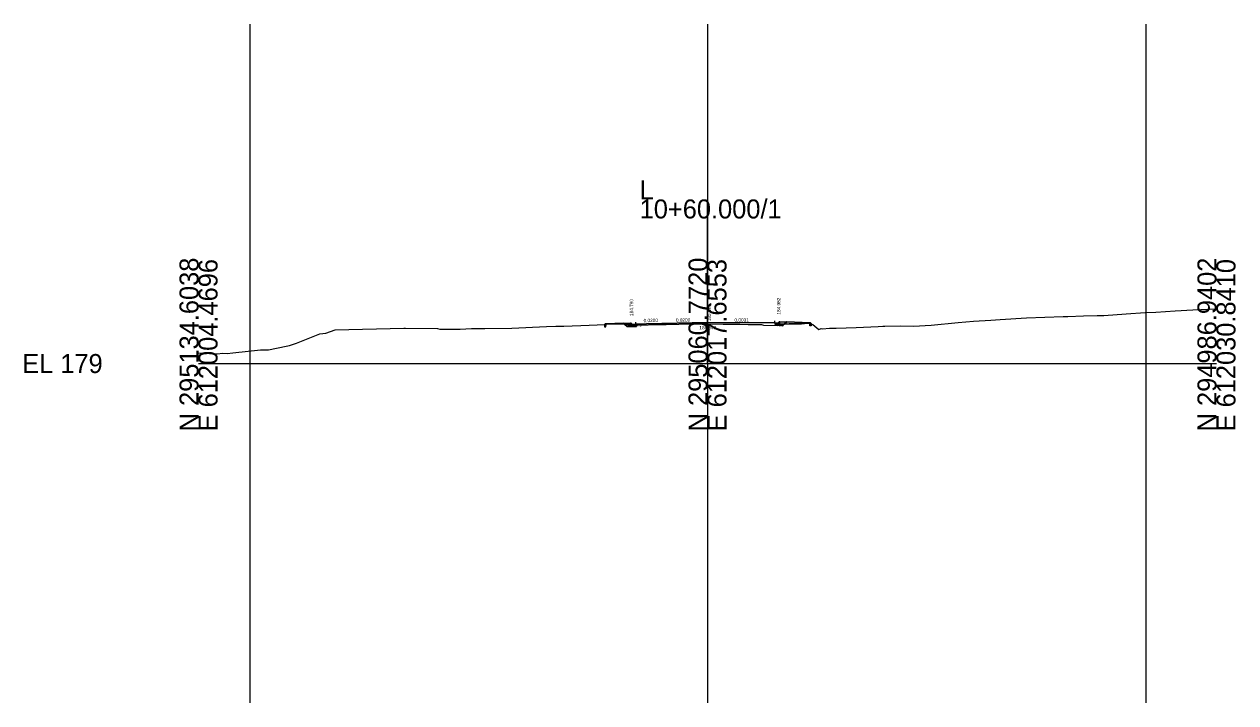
# Model space of a CAD drawing. Extents: x -81 to 616364, y 450 to 299952.
# Drawn here: x 535426.7 to 535605.2, y 116298.4 to 116398.4 of the extents above; entities that cross this region are included whole.
import ezdxf

# ---------------------------------------------------------------- set-up
doc = ezdxf.new("R2010")
doc.units = 0
for name, color, linetype in [('Exist XS Ground Line', 7, 'Continuous'), ('Old_Level_10', 7, 'Continuous'), ('Old_Level_17', 7, 'Continuous'), ('Old_Level_63', 7, 'Continuous'), ('Prop XS Dump Level', 7, 'Continuous'), ('Prop XS Earthwork Shape', 7, 'Continuous'), ('Prop XS EOT Tick Mark', 7, 'Continuous'), ('Prop XS Exc Vertical Line 1', 7, 'Continuous'), ('Prop XS Exc Vertical Line 2', 7, 'Continuous'), ('Prop XS Exc Vertical Line 3', 7, 'Continuous'), ('Prop XS Finish Grade', 7, 'Continuous'), ('Prop XS Finish Grade Concrete', 7, 'Continuous'), ('Prop XS Finish Grade Earthwork', 7, 'Continuous'), ('Prop XS Finish Grade Pavement', 7, 'Continuous'), ('Prop XS Pvmt Edge Slope', 7, 'Continuous'), ('Prop XS Side Slope Text', 7, 'Continuous'), ('Prop XS Subgrade Concrete', 7, 'Continuous'), ('Prop XS Subgrade Earthwork', 7, 'Continuous')]:
    doc.layers.add(name, color=color, linetype=linetype)

msp = doc.modelspace()

# ---------------------------------------------------------------- linework, layer by layer
at = {"layer": 'Exist XS Ground Line'}
for points in [[(535553.5, 116353.89), (535555.78, 116353.9), (535557.73, 116353.89), (535560.3, 116354.02), (535564.31, 116354.41), (535566.58, 116354.6), (535569.09, 116354.77), (535570.49, 116354.87), (535574.39, 116355.1), (535579.79, 116355.27), (535580.46, 116355.3), (535582.79, 116355.4), (535584.8, 116355.44), (535585.75, 116355.46), (535589.03, 116355.68), (535591.86, 116355.9), (535593.43, 116355.95), (535596.29, 116356.15), (535598.9, 116356.29), (535602.36, 116356.42)], [(535452.36, 116349.93), (535454.83, 116349.78), (535455.08, 116349.81), (535455.94, 116349.89), (535456.56, 116349.86), (535457.42, 116349.96), (535461.5, 116350.39), (535462.69, 116350.38), (535465.28, 116350.92), (535465.77, 116351.03), (535466.81, 116351.37), (535470.25, 116352.73), (535471.14, 116352.85), (535472.51, 116353.35), (535482.62, 116353.56), (535482.84, 116353.55), (535487.58, 116353.53), (535487.94, 116353.44), (535488.91, 116353.44), (535490.91, 116353.42), (535492.57, 116353.5), (535494.53, 116353.52), (535498.52, 116353.58), (535503.64, 116353.8), (535504.99, 116353.85), (535505.43, 116353.86), (535506.19, 116353.88), (535509.92, 116354.03), (535512.26, 116354.1), (535512.4, 116354.1), (535512.55, 116354.2), (535515.87, 116354.15), (535516.6, 116354.13), (535516.9, 116354.13), (535517.05, 116354.03), (535520.25, 116354.11), (535520.36, 116354.13), (535521.26, 116354.13), (535525, 116354.2), (535525.17, 116354.2), (535527.27, 116354.21), (535529.68, 116354.18), (535532.14, 116354.15), (535533.37, 116354.13), (535535.3, 116354.09), (535535.6, 116354.03), (535537.71, 116353.98), (535537.87, 116354.14), (535539.4, 116354.19), (535539.87, 116354.21), (535541.2, 116354.22), (535542.14, 116354.31), (535542.36, 116354.33), (535542.51, 116354.23), (535542.62, 116354.23), (535542.88, 116354.11), (535543.78, 116353.4), (535544.09, 116353.51), (535544.31, 116353.45), (535545.34, 116353.57), (535546.31, 116353.59), (535549.25, 116353.65), (535552.53, 116353.84), (535553.22, 116353.87), (535553.5, 116353.89)]]:
    msp.add_lwpolyline(points, dxfattribs=at)
at = {"layer": 'Old_Level_10'}
for p, q in [((535542.45, 116354.26), (535542.45, 116354.36)), ((535512.37, 116354.1), (535512.37, 116354.22))]:
    msp.add_line(p, q, dxfattribs=at)
msp.add_arc((535512.38, 116354.17), 0.00196, 145.5013, 214.4987, dxfattribs=at)
at = {"layer": 'Old_Level_17'}
for p, q in [((535542.45, 116354.35), (535542.46, 116354.36)), ((535542.48, 116354.35), (535542.45, 116354.34)), ((535542.46, 116354.36), (535542.51, 116354.36)), ((535542.47, 116354.36), (535542.48, 116354.35)), ((535542.54, 116354.35), (535542.65, 116354.24)), ((535542.54, 116354.35), (535542.54, 116354.35)), ((535512.29, 116354.21), (535512.17, 116354.1)), ((535512.17, 116354.1), (535512.17, 116353.77)), ((535512.37, 116354.07), (535512.17, 116354.07)), ((535512.17, 116354.02), (535512.19, 116354.02)), ((535512.18, 116354), (535512.17, 116354)), ((535512.18, 116353.93), (535512.17, 116353.93)), ((535512.17, 116353.91), (535512.19, 116353.9)), ((535512.17, 116353.77), (535512.37, 116353.77)), ((535512.19, 116354.02), (535512.18, 116354)), ((535512.19, 116353.9), (535512.18, 116353.93)), ((535512.24, 116354.11), (535512.27, 116354.12)), ((535512.28, 116354.1), (535512.24, 116354.11)), ((535512.24, 116353.82), (535512.27, 116353.83)), ((535512.28, 116353.81), (535512.24, 116353.82)), ((535512.27, 116354.12), (535512.28, 116354.1)), ((535512.27, 116353.83), (535512.28, 116353.81)), ((535512.29, 116354.21), (535512.29, 116354.21)), ((535512.37, 116354.22), (535512.32, 116354.22)), ((535512.36, 116354.22), (535512.35, 116354.21)), ((535512.35, 116354.21), (535512.37, 116354.21)), ((535512.37, 116354.01), (535512.35, 116354.04)), ((535512.35, 116354.04), (535512.37, 116354.04)), ((535512.36, 116353.95), (535512.35, 116353.92)), ((535512.35, 116353.92), (535512.37, 116353.92)), ((535512.37, 116353.92), (535512.36, 116353.95)), ((535512.37, 116354.22), (535512.37, 116354.22)), ((535512.37, 116353.77), (535512.37, 116354.1)), ((535542.45, 116353.91), (535542.45, 116354.26)), ((535542.45, 116354.21), (535542.65, 116354.21)), ((535542.48, 116354.17), (535542.45, 116354.18)), ((535542.45, 116354.15), (535542.48, 116354.17)), ((535542.45, 116354.06), (535542.47, 116354.08)), ((535542.48, 116354.05), (535542.45, 116354.05)), ((535542.65, 116353.91), (535542.45, 116353.91)), ((535542.47, 116354.08), (535542.48, 116354.05)), ((535542.56, 116354.26), (535542.55, 116354.24)), ((535542.55, 116354.24), (535542.59, 116354.25)), ((535542.56, 116353.97), (535542.55, 116353.95)), ((535542.55, 116353.95), (535542.59, 116353.96)), ((535542.59, 116354.25), (535542.56, 116354.26)), ((535542.59, 116353.96), (535542.56, 116353.97)), ((535542.63, 116354.04), (535542.65, 116354.07)), ((535542.65, 116354.05), (535542.63, 116354.04)), ((535542.64, 116354.16), (535542.65, 116354.14)), ((535542.65, 116354.15), (535542.64, 116354.16)), ((535542.65, 116354.24), (535542.65, 116353.91)), ((535542.65, 116354.14), (535542.65, 116354.14)), ((535542.65, 116354.07), (535542.65, 116354.07))]:
    msp.add_line(p, q, dxfattribs=at)
for centre in [(535512.18, 116353.96), (535512.2, 116354.08), (535512.2, 116353.79), (535512.22, 116354.12), (535512.21, 116353.98), (535512.22, 116353.83), (535512.23, 116354.08), (535512.22, 116354.04), (535512.22, 116353.88), (535512.23, 116353.79), (535512.25, 116353.94), (535512.26, 116354.15), (535512.27, 116354.06), (535512.26, 116353.86), (535512.27, 116354.18), (535512.27, 116354.02), (535512.27, 116353.98), (535512.28, 116353.97), (535512.27, 116353.89), (535512.28, 116353.93), (535512.3, 116354.16), (535512.3, 116354.1), (535512.3, 116354.02), (535512.3, 116353.87), (535512.3, 116353.81), (535512.32, 116354.07), (535512.33, 116353.97), (535512.32, 116353.95), (535512.35, 116354.12), (535512.35, 116353.83), (535512.35, 116354.17), (535512.35, 116353.88), (535512.36, 116353.99), (535542.47, 116354.13), (535542.48, 116354.3), (535542.48, 116354.26), (535542.48, 116354.01), (535542.48, 116353.97), (535542.5, 116354.11), (535542.51, 116354.2), (535542.51, 116354.09), (535542.53, 116354.15), (535542.53, 116354.3), (535542.53, 116354.24), (535542.53, 116354.01), (535542.53, 116353.95), (535542.56, 116354.32), (535542.55, 116354.11), (535542.55, 116354.07), (535542.56, 116354.03), (535542.56, 116354.2), (535542.56, 116354.16), (535542.56, 116354.12), (535542.57, 116354.29), (535542.57, 116354), (535542.58, 116354.07), (535542.6, 116354.22), (535542.6, 116353.93), (535542.61, 116354.26), (535542.61, 116354.17), (535542.61, 116354.02), (535542.61, 116353.97), (535542.62, 116354.11), (535542.63, 116354.22), (535542.63, 116353.93), (535542.65, 116354.1)]:
    msp.add_circle(centre, 0.00196, dxfattribs=at)
for centre, radius, start, end in [((535542.46, 116354.36), 0.006, 90, 180), ((535542.51, 116354.31), 0.05, 45, 90), ((535512.18, 116353.87), 0.00196, 256.8767, 103.1233), ((535512.27, 116353.77), 0.00196, 24.915, 155.085), ((535512.32, 116354.17), 0.05, 90, 135), ((535512.32, 116353.78), 0.00196, 342.3416, 197.6584), ((535512.37, 116354.22), 0.006, 0, 90), ((535512.37, 116353.96), 0.00196, 17.8106, 342.1894), ((535542.45, 116354.31), 0.00196, 325.5013, 34.4987), ((535542.46, 116354.1), 0.00196, 197.8106, 162.1894), ((535542.51, 116353.91), 0.00196, 342.3416, 197.6584), ((535542.56, 116353.91), 0.00196, 24.915, 155.085), ((535542.65, 116354.01), 0.00196, 76.8767, 283.1233)]:
    msp.add_arc(centre, radius, start, end, dxfattribs=at)
at = {"layer": 'Old_Level_63'}
for p, q in [((535527.36, 116348.36), (535527.36, 116372.54)), ((535452.36, 116348.36), (535527.36, 116348.36)), ((535527.36, 116348.36), (535602.36, 116348.36))]:
    msp.add_line(p, q, dxfattribs=at)
at = {"layer": 'Prop XS Dump Level'}
for p, q in [((535518.36, 116354.21), (535527.36, 116354.39)), ((535527.36, 116354.39), (535537.26, 116354.36)), ((535516.76, 116354.18), (535518.36, 116354.21))]:
    msp.add_line(p, q, dxfattribs=at)
at = {"layer": 'Prop XS Earthwork Shape'}
for points in [[(535538.68, 116354.17), (535539.03, 116354.52), (535542.45, 116354.36), (535542.45, 116354.26), (535542.36, 116354.33), (535542.14, 116354.31), (535541.2, 116354.22), (535539.87, 116354.21), (535539.4, 116354.19)], [(535538.68, 116354.17), (535539.4, 116354.19), (535539.87, 116354.21), (535541.2, 116354.22), (535542.14, 116354.31), (535542.36, 116354.33), (535542.45, 116354.26), (535542.45, 116354.36), (535539.03, 116354.52)], [(535538.68, 116354.17), (535539.4, 116354.19), (535539.87, 116354.21), (535541.2, 116354.22), (535542.14, 116354.31), (535542.36, 116354.33), (535542.45, 116354.26), (535542.45, 116354.36), (535539.03, 116354.52)], [(535542.45, 116354.36), (535542.45, 116354.26), (535542.36, 116354.33), (535542.14, 116354.31), (535541.2, 116354.22), (535539.87, 116354.21), (535539.4, 116354.19), (535538.68, 116354.17), (535539.03, 116354.52)], [(535538.68, 116354.17), (535539.4, 116354.19), (535539.87, 116354.21), (535541.2, 116354.22), (535542.14, 116354.31), (535542.36, 116354.33), (535542.45, 116354.26), (535542.45, 116354.36), (535539.03, 116354.52)], [(535538.68, 116354.17), (535539.4, 116354.19), (535539.87, 116354.21), (535541.2, 116354.22), (535542.14, 116354.31), (535542.36, 116354.33), (535542.45, 116354.26), (535542.45, 116354.36), (535539.03, 116354.52)], [(535538.68, 116354.17), (535539.4, 116354.19), (535539.87, 116354.21), (535541.2, 116354.22), (535542.14, 116354.31), (535542.36, 116354.33), (535542.45, 116354.26), (535542.45, 116354.36), (535539.03, 116354.52)], [(535512.37, 116354.22), (535514.99, 116354.33), (535515.15, 116354.16), (535512.55, 116354.2), (535512.4, 116354.1), (535512.37, 116354.1)], [(535512.37, 116354.1), (535512.4, 116354.1), (535512.55, 116354.2), (535515.15, 116354.16), (535514.99, 116354.33), (535512.37, 116354.22)], [(535512.37, 116354.1), (535512.4, 116354.1), (535512.55, 116354.2), (535515.15, 116354.16), (535514.99, 116354.33), (535512.37, 116354.22)], [(535512.37, 116354.22), (535514.99, 116354.33), (535515.15, 116354.16), (535512.55, 116354.2), (535512.37, 116354.1)], [(535512.37, 116354.1), (535512.4, 116354.1), (535512.55, 116354.2), (535515.15, 116354.16), (535514.99, 116354.33), (535512.37, 116354.22)], [(535512.37, 116354.1), (535512.4, 116354.1), (535512.55, 116354.2), (535515.15, 116354.16), (535514.99, 116354.33), (535512.37, 116354.22)], [(535512.37, 116354.1), (535512.4, 116354.1), (535512.55, 116354.2), (535515.15, 116354.16), (535514.99, 116354.33), (535512.37, 116354.22)], [(535515.51, 116353.8), (535516.76, 116353.8), (535516.9, 116353.8), (535516.9, 116354.13), (535516.6, 116354.13), (535515.87, 116354.15), (535515.15, 116354.16)], [(535515.15, 116354.16), (535515.87, 116354.15), (535516.6, 116354.13), (535516.9, 116354.13), (535516.9, 116353.8), (535516.76, 116353.8), (535515.51, 116353.8)], [(535515.15, 116354.16), (535515.87, 116354.15), (535516.6, 116354.13), (535516.9, 116354.13), (535516.9, 116353.8), (535516.76, 116353.8), (535515.51, 116353.8)], [(535515.51, 116353.8), (535516.76, 116353.8), (535516.9, 116353.8), (535516.9, 116354.13), (535516.6, 116354.13), (535515.87, 116354.15), (535515.15, 116354.16)], [(535515.15, 116354.16), (535515.87, 116354.15), (535516.6, 116354.13), (535516.9, 116354.13), (535516.9, 116353.8), (535516.76, 116353.8), (535515.51, 116353.8)], [(535515.15, 116354.16), (535515.87, 116354.15), (535516.6, 116354.13), (535516.9, 116354.13), (535516.9, 116353.8), (535516.76, 116353.8), (535515.51, 116353.8)], [(535515.15, 116354.16), (535515.87, 116354.15), (535516.6, 116354.13), (535516.9, 116354.13), (535516.9, 116353.8), (535516.76, 116353.8), (535515.51, 116353.8)], [(535537.26, 116353.99), (535537.64, 116353.99), (535537.26, 116353.98)], [(535537.26, 116353.99), (535537.64, 116353.99), (535537.26, 116353.98)], [(535537.26, 116353.99), (535537.64, 116353.99), (535537.26, 116353.98)], [(535537.71, 116353.99), (535537.87, 116354.14), (535538.68, 116354.17), (535538.51, 116354)], [(535537.71, 116353.99), (535537.87, 116354.14), (535538.68, 116354.17), (535538.51, 116354)], [(535537.71, 116353.99), (535537.87, 116354.14), (535538.68, 116354.17), (535538.51, 116354)], [(535538.51, 116354), (535538.68, 116354.17), (535537.87, 116354.14), (535537.71, 116353.98)], [(535537.71, 116353.99), (535538.51, 116354), (535538.68, 116354.17), (535537.87, 116354.14)], [(535537.71, 116353.99), (535538.51, 116354), (535538.68, 116354.17), (535537.87, 116354.14)], [(535537.71, 116353.99), (535538.51, 116354), (535538.68, 116354.17), (535537.87, 116354.14)]]:
    msp.add_lwpolyline(points, close=True, dxfattribs=at)
at = {"layer": 'Prop XS EOT Tick Mark'}
for p, q in [((535516.76, 116354.48), (535516.76, 116354.18)), ((535537.26, 116354.36), (535537.26, 116354.67))]:
    msp.add_line(p, q, dxfattribs=at)
at = {"layer": 'Prop XS Exc Vertical Line 1'}
msp.add_line((535459.94, 116398.36), (535459.94, 116298.36), dxfattribs=at)
at = {"layer": 'Prop XS Exc Vertical Line 2'}
msp.add_line((535527.36, 116398.36), (535527.36, 116298.36), dxfattribs=at)
at = {"layer": 'Prop XS Exc Vertical Line 3'}
msp.add_line((535591.96, 116398.36), (535591.96, 116298.36), dxfattribs=at)
at = {"layer": 'Prop XS Finish Grade'}
for p, q in [((535538.01, 116354.5), (535539.03, 116354.52)), ((535514.99, 116354.33), (535516.01, 116354.3))]:
    msp.add_line(p, q, dxfattribs=at)
at = {"layer": 'Prop XS Finish Grade Concrete'}
for p, q in [((535537.26, 116354.36), (535537.79, 116354.35)), ((535537.79, 116354.35), (535537.83, 116354.36)), ((535537.83, 116354.36), (535537.85, 116354.38)), ((535537.85, 116354.38), (535537.87, 116354.46)), ((535537.87, 116354.46), (535537.9, 116354.49)), ((535537.94, 116354.5), (535537.9, 116354.49)), ((535538.01, 116354.5), (535537.94, 116354.5)), ((535516.09, 116354.3), (535516.01, 116354.3)), ((535516.13, 116354.3), (535516.09, 116354.3)), ((535516.13, 116354.3), (535516.15, 116354.27)), ((535516.15, 116354.27), (535516.18, 116354.19)), ((535516.18, 116354.19), (535516.2, 116354.16)), ((535516.2, 116354.16), (535516.24, 116354.16)), ((535516.24, 116354.16), (535516.76, 116354.18))]:
    msp.add_line(p, q, dxfattribs=at)
at = {"layer": 'Prop XS Finish Grade Earthwork'}
for p, q in [((535539.03, 116354.52), (535542.45, 116354.36)), ((535542.45, 116354.36), (535542.45, 116354.26)), ((535512.37, 116354.22), (535514.99, 116354.33)), ((535512.37, 116354.22), (535512.37, 116354.1))]:
    msp.add_line(p, q, dxfattribs=at)
at = {"layer": 'Prop XS Finish Grade Pavement'}
for p, q in [((535527.36, 116354.39), (535518.36, 116354.21)), ((535537.26, 116354.36), (535527.36, 116354.39)), ((535518.36, 116354.21), (535516.76, 116354.18))]:
    msp.add_line(p, q, dxfattribs=at)
at = {"layer": 'Prop XS Pvmt Edge Slope'}
for p, q in [((535515.51, 116353.8), (535515.71, 116354)), ((535515.71, 116354), (535516.01, 116354)), ((535538.01, 116354.19), (535538.31, 116354.2)), ((535538.31, 116354.2), (535538.51, 116354))]:
    msp.add_line(p, q, dxfattribs=at)
at = {"layer": 'Prop XS Subgrade Concrete'}
for p, q in [((535537.26, 116354.36), (535537.26, 116354.18)), ((535538.01, 116354.19), (535538.01, 116354.5)), ((535516.01, 116354.3), (535516.01, 116354)), ((535516.01, 116354), (535516.76, 116354)), ((535516.76, 116354), (535516.76, 116354.18)), ((535537.26, 116354.18), (535538.01, 116354.19))]:
    msp.add_line(p, q, dxfattribs=at)
at = {"layer": 'Prop XS Subgrade Earthwork'}
for p, q in [((535538.51, 116354), (535539.03, 116354.52)), ((535514.99, 116354.33), (535515.51, 116353.8)), ((535515.51, 116353.8), (535516.76, 116353.8)), ((535516.76, 116353.8), (535516.9, 116353.8)), ((535516.9, 116354.13), (535516.9, 116353.8)), ((535537.64, 116353.99), (535538.51, 116354))]:
    msp.add_line(p, q, dxfattribs=at)

# ---------------------------------------------------------------- texts
at = {"layer": 'Old_Level_63'}
for s, p in [('L', (535517.36, 116372.54)), ('10+60.000/1', (535517.36, 116369.74)), ('EL 179', (535426.37, 116346.96))]:
    msp.add_text(s, height=2.8, dxfattribs=at).set_placement(p)
for s, p in [('N 295134.6038', (535452.36, 116338.36)), ('E 612004.4696', (535455.16, 116338.36)), ('N 295060.7720', (535527.36, 116338.36)), ('E 612017.6553', (535530.16, 116338.36)), ('N 294986.9402', (535602.36, 116338.36)), ('E 612030.8410', (535605.16, 116338.36))]:
    msp.add_text(s, height=2.8, rotation=90, dxfattribs=at).set_placement(p)
at = {"layer": 'Prop XS Dump Level'}
for p in [(535516.9, 116353.83), (535537.87, 116353.84)]:
    msp.add_text('Eop', height=0.3, dxfattribs=at).set_placement(p)
at = {"layer": 'Prop XS Side Slope Text'}
for s, rotation, p in [('184.982', 90, (535538.11, 116355.57)), ('184.790', 90, (535516.41, 116355.37)), (' 185.026', 90, (535527.86, 116354.39)), ('0.0200', 1.1458, (535517.95, 116354.44)), ('0.0200', 1.1458, (535522.71, 116354.5)), ('0.0031', 359.8248, (535531.33, 116354.53))]:
    msp.add_text(s, height=0.5, rotation=rotation, dxfattribs=at).set_placement(p)
msp.add_text('184.840', height=0.5, dxfattribs=at).set_placement((535526.15, 116353.41))

doc.saveas('drawing.dxf')
